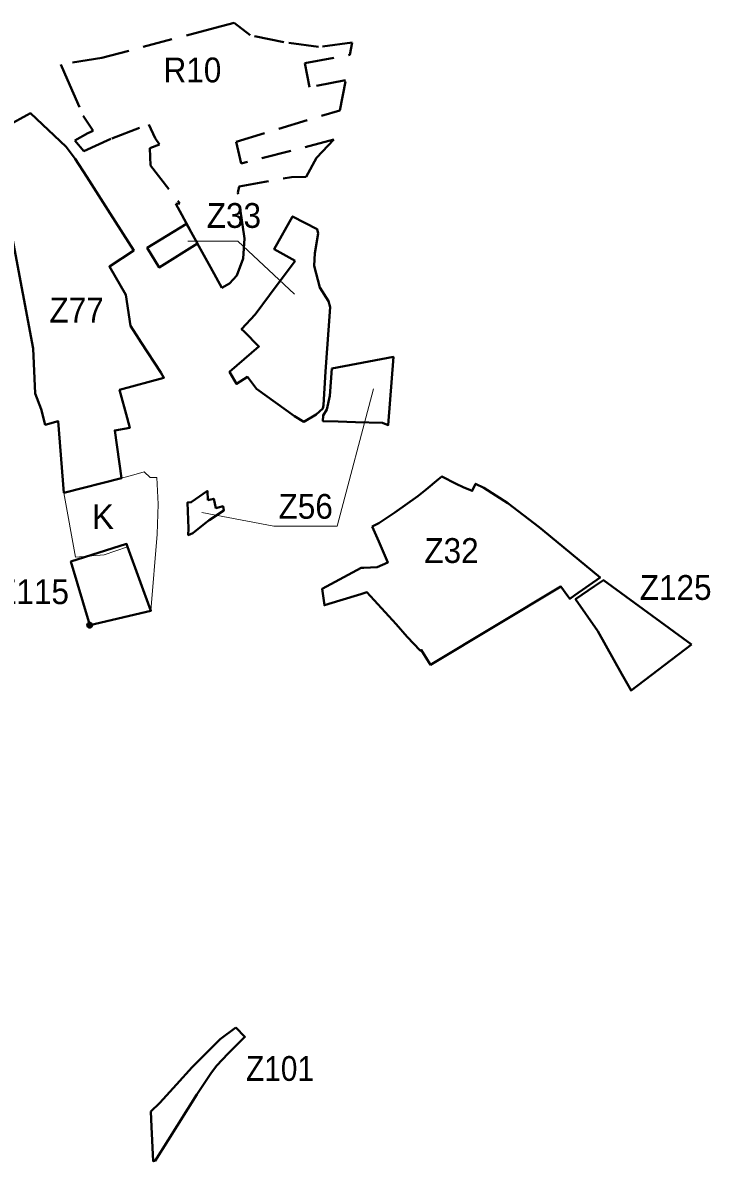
# Model space of a CAD drawing. Extents: x -650276 to -642489, y -1074311 to -1066658.
# Drawn here: x -645184 to -644519, y -1073665 to -1072562 of the extents above; entities that cross this region are included whole.
import ezdxf

# ---------------------------------------------------------------- set-up
doc = ezdxf.new("R2010")
doc.units = 0
doc.header["$LTSCALE"] = 9.6
doc.header["$PDMODE"] = 32
doc.header["$PDSIZE"] = 4.8
doc.linetypes.add('MEDIUM_DASHED', pattern=[4.5, 3, -1.5])
for name, color, linetype, lineweight in [('42', 7, 'Continuous', 25), ('44', 7, 'Continuous', 40), ('45', 7, 'Continuous', 40), ('46', 7, 'Continuous', 13), ('47', 7, 'Continuous', 13), ('48', 7, 'Continuous', 13), ('61', 7, 'MEDIUM_DASHED', 40), ('62', 7, 'Continuous', 35)]:
    doc.layers.add(name, color=color, linetype=linetype, lineweight=lineweight)

msp = doc.modelspace()

# ---------------------------------------------------------------- linework, layer by layer
at = {"layer": '42'}
msp.add_lwpolyline([(-644845.72, -1073050.14), (-644839.57, -1073064.5), (-644830.81, -1073084.98), (-644840.89, -1073089.3), (-644853.8, -1073089.99), (-644856.4, -1073090.13), (-644894.15, -1073110.3), (-644892.14, -1073126.36), (-644877.32, -1073121.83), (-644856.97, -1073115.6), (-644851, -1073113.77), (-644822.62, -1073144.71), (-644811.96, -1073156.75), (-644799.26, -1073170.13), (-644798.38, -1073169.56), (-644792.59, -1073178.73), (-644789.31, -1073183.93), (-644663.17, -1073108.27), (-644656.56, -1073117.4), (-644654.61, -1073120.1), (-644649.7, -1073116.65), (-644625.26, -1073099.51), (-644680.69, -1073053.67), (-644684.09, -1073050.8), (-644714.42, -1073027.62), (-644714.42, -1073027.62), (-644737.88, -1073012.62), (-644745.73, -1073008.64), (-644748.95, -1073015.64), (-644757.73, -1073012.05), (-644764.69, -1073008.87), (-644778.38, -1073001.84), (-644781.52, -1073004.39), (-644793.743, -1073014.293), (-644801.54, -1073020.61), (-644824.08, -1073036.56), (-644832.7, -1073042.34), (-644839.47, -1073046.89)], close=True, dxfattribs=at)
at = {"layer": '44'}
msp.add_lwpolyline([(-644977.924, -1073535.072), (-644969.117, -1073544.254), (-644985.66, -1073560.69), (-644996.41, -1073571.97), (-645001.267, -1073578.582), (-645015.55, -1073599.96), (-645043.35, -1073644.04), (-645056.06, -1073664.2), (-645057.87, -1073664.55), (-645059.35, -1073631.3), (-645060.009, -1073616.53), (-645051.513, -1073608.124), (-645035.303, -1073590.199), (-645020.11, -1073573.585), (-644993.044, -1073546.324)], close=True, dxfattribs=at)
at = {"layer": '45'}
for points in [[(-645144.37, -1073017.64), (-645088.62, -1073003.45), (-645095.04, -1072957.07), (-645080.61, -1072954.43), (-645083.13, -1072944.94), (-645090.34, -1072917.86), (-645047.42, -1072906.05), (-645050.6, -1072901.03), (-645069.55, -1072872.12), (-645071.87, -1072868.45), (-645079.81, -1072855.89), (-645084.47, -1072825.67), (-645100.27, -1072798.46), (-645076.66, -1072783.06), (-645099.58, -1072746.945), (-645121.96, -1072711.68), (-645133.26, -1072694.17), (-645142.1, -1072682.57), (-645176.757, -1072649.968), (-645180.05, -1072651.77), (-645213.34, -1072669.98), (-645174.13, -1072877.93), (-645172.28, -1072921.42), (-645166.48, -1072936.5), (-645162.379, -1072951.55), (-645149.84, -1072948.13)], [(-645025.61, -1072757.17), (-645063.6, -1072780.26), (-645051.94, -1072799.21), (-645015.02, -1072776.01)], [(-645025.61, -1072757.17), (-645063.6, -1072780.26), (-645051.94, -1072799.21), (-645015.02, -1072776.01)], [(-644884.94, -1072897.19), (-644886.98, -1072923.48), (-644889.65, -1072936.67), (-644893.37, -1072942.61), (-644893.59, -1072947.97), (-644878.86, -1072948.42), (-644861.93, -1072948.94), (-644835.99, -1072949.74), (-644830.25, -1072951.9), (-644825.25, -1072885.96)], [(-644884.94, -1072897.19), (-644886.98, -1072923.48), (-644889.65, -1072936.67), (-644893.37, -1072942.61), (-644893.59, -1072947.97), (-644878.86, -1072948.42), (-644861.93, -1072948.94), (-644835.99, -1072949.74), (-644830.25, -1072951.9), (-644825.25, -1072885.96)], [(-644845.72, -1073050.14), (-644839.57, -1073064.5), (-644830.81, -1073084.98), (-644840.89, -1073089.3), (-644853.8, -1073089.99), (-644856.4, -1073090.13), (-644894.15, -1073110.3), (-644892.14, -1073126.36), (-644877.32, -1073121.83), (-644856.97, -1073115.6), (-644851, -1073113.77), (-644822.62, -1073144.71), (-644811.96, -1073156.75), (-644799.26, -1073170.13), (-644798.38, -1073169.56), (-644792.59, -1073178.73), (-644789.31, -1073183.93), (-644663.17, -1073108.27), (-644656.56, -1073117.4), (-644654.61, -1073120.1), (-644649.7, -1073116.65), (-644625.26, -1073099.51), (-644680.69, -1073053.67), (-644684.09, -1073050.8), (-644714.42, -1073027.62), (-644714.42, -1073027.62), (-644737.88, -1073012.62), (-644745.73, -1073008.64), (-644748.95, -1073015.64), (-644757.73, -1073012.05), (-644764.69, -1073008.87), (-644778.38, -1073001.84), (-644781.52, -1073004.39), (-644793.743, -1073014.293), (-644801.54, -1073020.61), (-644824.08, -1073036.56), (-644832.7, -1073042.34), (-644839.47, -1073046.89)], [(-644845.72, -1073050.14), (-644839.57, -1073064.5), (-644830.81, -1073084.98), (-644840.89, -1073089.3), (-644853.8, -1073089.99), (-644856.4, -1073090.13), (-644894.15, -1073110.3), (-644892.14, -1073126.36), (-644877.32, -1073121.83), (-644856.97, -1073115.6), (-644851, -1073113.77), (-644822.62, -1073144.71), (-644811.96, -1073156.75), (-644799.26, -1073170.13), (-644798.38, -1073169.56), (-644792.59, -1073178.73), (-644789.31, -1073183.93), (-644663.17, -1073108.27), (-644656.56, -1073117.4), (-644654.61, -1073120.1), (-644649.7, -1073116.65), (-644625.26, -1073099.51), (-644680.69, -1073053.67), (-644684.09, -1073050.8), (-644714.42, -1073027.62), (-644714.42, -1073027.62), (-644737.88, -1073012.62), (-644745.73, -1073008.64), (-644748.95, -1073015.64), (-644757.73, -1073012.05), (-644764.69, -1073008.87), (-644778.38, -1073001.84), (-644781.52, -1073004.39), (-644793.743, -1073014.293), (-644801.54, -1073020.61), (-644824.08, -1073036.56), (-644832.7, -1073042.34), (-644839.47, -1073046.89)], [(-645004.82, -1073024.63), (-645005.31, -1073015.68), (-645021.1, -1073026.69), (-645024.71, -1073026.95), (-645023.6, -1073052.12), (-645023.88, -1073058.37), (-645019.57, -1073056.46), (-645007.99, -1073047.31), (-645003.78, -1073043.96), (-644989.34, -1073034.58), (-644990.25, -1073030.54), (-644997.09, -1073032.21), (-644999.23, -1073023.29)], [(-645004.82, -1073024.63), (-645005.31, -1073015.68), (-645021.1, -1073026.69), (-645024.71, -1073026.95), (-645023.6, -1073052.12), (-645023.88, -1073058.37), (-645019.57, -1073056.46), (-645007.99, -1073047.31), (-645003.78, -1073043.96), (-644989.34, -1073034.58), (-644990.25, -1073030.54), (-644997.09, -1073032.21), (-644999.23, -1073023.29)], [(-645119.34, -1073145.61), (-645060.1, -1073131.68), (-645082.6, -1073069.93), (-645083.681, -1073066.962), (-645137.5, -1073083.97)]]:
    msp.add_lwpolyline(points, close=True, dxfattribs=at)
for points in [[(-644902.18, -1072797.88), (-644901.35, -1072785.36), (-644898.29, -1072766.55), (-644899.2, -1072762.14), (-644922.88, -1072749.97), (-644940.8, -1072781.48), (-644920.46, -1072792.92)], [(-644902.18, -1072797.88), (-644901.35, -1072785.36), (-644898.29, -1072766.55), (-644899.2, -1072762.14), (-644922.88, -1072749.97), (-644940.8, -1072781.48), (-644920.46, -1072792.92)], [(-644920.46, -1072792.92), (-644945.2, -1072826.3), (-644959.24, -1072844.92), (-644972.28, -1072859.02), (-644969.93, -1072861.43), (-644955.49, -1072875.78), (-644983.93, -1072900.24), (-644977.16, -1072912.11), (-644966.57, -1072905.23), (-644957.79, -1072916.73), (-644921.18, -1072943.17), (-644911.87, -1072948.76), (-644900.2, -1072941.67), (-644893.77, -1072935.88), (-644892.86, -1072932.6), (-644891.2, -1072900.09), (-644886.61, -1072837.61), (-644887.99, -1072831.83), (-644896.45, -1072818.78), (-644902.18, -1072797.88)], [(-644920.46, -1072792.92), (-644945.2, -1072826.3), (-644959.24, -1072844.92), (-644972.28, -1072859.02), (-644969.93, -1072861.43), (-644955.49, -1072875.78), (-644983.93, -1072900.24), (-644977.16, -1072912.11), (-644966.57, -1072905.23), (-644957.79, -1072916.73), (-644921.18, -1072943.17), (-644911.87, -1072948.76), (-644900.2, -1072941.67), (-644893.77, -1072935.88), (-644892.86, -1072932.6), (-644891.2, -1072900.09), (-644886.61, -1072837.61), (-644887.99, -1072831.83), (-644896.45, -1072818.78), (-644902.18, -1072797.88)], [(-644536.62, -1073164.33), (-644622.03, -1073101.88), (-644630.58, -1073107.78), (-644648.95, -1073120.47), (-644627.53, -1073151.26)], [(-644627.53, -1073151.26), (-644604.13, -1073193), (-644595.18, -1073208.98), (-644536.62, -1073164.33)]]:
    msp.add_lwpolyline(points, dxfattribs=at)
msp.add_point((-645119.34, -1073145.61), dxfattribs=at)
at = {"layer": '46'}
for points in [[(-645024.402, -1072773.758), (-644975.968, -1072773.758), (-644921.076, -1072825.098)], [(-644844.691, -1072916.725), (-644879.683, -1073049.795), (-644940.921, -1073049.795), (-645010.906, -1073036.663)], [(-644844.691, -1072916.725), (-644879.683, -1073049.795), (-644940.921, -1073049.795), (-645010.906, -1073036.663)]]:
    msp.add_lwpolyline(points, dxfattribs=at)
at = {"layer": '47'}
msp.add_line((-645082.6, -1073069.93), (-645060.1, -1073131.68), dxfattribs=at)
for points in [[(-645060.95, -1073002.68), (-645066.66, -1072997.3), (-645066.66, -1072997.3), (-645074.312, -1072999.359), (-645088.62, -1073003.45)], [(-645060.1, -1073131.68), (-645054.12, -1073057.62), (-645052.94, -1073028.58), (-645054.44, -1073002.54), (-645060.95, -1073002.68)], [(-645088.62, -1073003.45), (-645144.37, -1073017.64), (-645133.18, -1073079.73), (-645105.39, -1073077.58), (-645082.6, -1073069.93)]]:
    msp.add_lwpolyline(points, dxfattribs=at)
at = {"layer": '61'}
msp.add_lwpolyline([(-645107.58, -1072596.47), (-645147.13, -1072602.79), (-645140.96, -1072617.82), (-645125.58, -1072652.42), (-645116.1, -1072667.08), (-645121.26, -1072669.32), (-645133.59, -1072676.49), (-645124.933, -1072686.721), (-645098.016, -1072674.425), (-645062.131, -1072660.856), (-645056.08, -1072674.07), (-645051.87, -1072680.22), (-645061.13, -1072683.98), (-645060.48, -1072700.69), (-645032.11, -1072737.28), (-645036.08, -1072737.88), (-645002.34, -1072799.06), (-644991.3, -1072819.12), (-644984.02, -1072814.87), (-644977, -1072807.06), (-644970.87, -1072790.69), (-644969.63, -1072771.21), (-644975.852, -1072727.059), (-644974.61, -1072720.9), (-644924.08, -1072711.8), (-644909.76, -1072711.64), (-644899.86, -1072693.27), (-644882.85, -1072675.56), (-644972.68, -1072698.65), (-644977.57, -1072677.66), (-644877.32, -1072647.4), (-644871.55, -1072618.07), (-644906.56, -1072624.79), (-644911.21, -1072601.67), (-644867.36, -1072593.58), (-644865.31, -1072581.58), (-644897.87, -1072585.78), (-644931.48, -1072581.26), (-644963.97, -1072574.57), (-644979.55, -1072562.44), (-644997.92, -1072567.23)], close=True, dxfattribs=at)

# ---------------------------------------------------------------- texts
at = {"layer": '44', "width": 0.9}
msp.add_text('Z101', height=24, dxfattribs=at).set_placement((-644967.996, -1073586.746))
msp.add_text('Z101', height=24, dxfattribs=at).set_placement((-644967.996, -1073586.746))
at = {"layer": '46', "width": 0.95}
for s, p in [('Z33', (-645005.989, -1072761.006)), ('Z77', (-645158.28, -1072852.64)), ('Z56', (-644936.499, -1073042.592)), ('Z56', (-644936.499, -1073042.592)), ('Z32', (-644795.309, -1073085.354)), ('Z32', (-644795.309, -1073085.354)), ('Z115', (-645208.897, -1073125.218)), ('Z125', (-644586.786, -1073121.127))]:
    msp.add_text(s, height=24, dxfattribs=at).set_placement(p)
at = {"layer": '48'}
msp.add_text('K', height=24, dxfattribs=at).set_placement((-645117.21, -1073052.527))
at = {"layer": '62', "width": 0.95}
msp.add_text('R10', height=24, dxfattribs=at).set_placement((-645047.84, -1072620.116))
msp.add_text('R10', height=24, dxfattribs=at).set_placement((-645047.84, -1072620.116))

doc.saveas('drawing.dxf')
